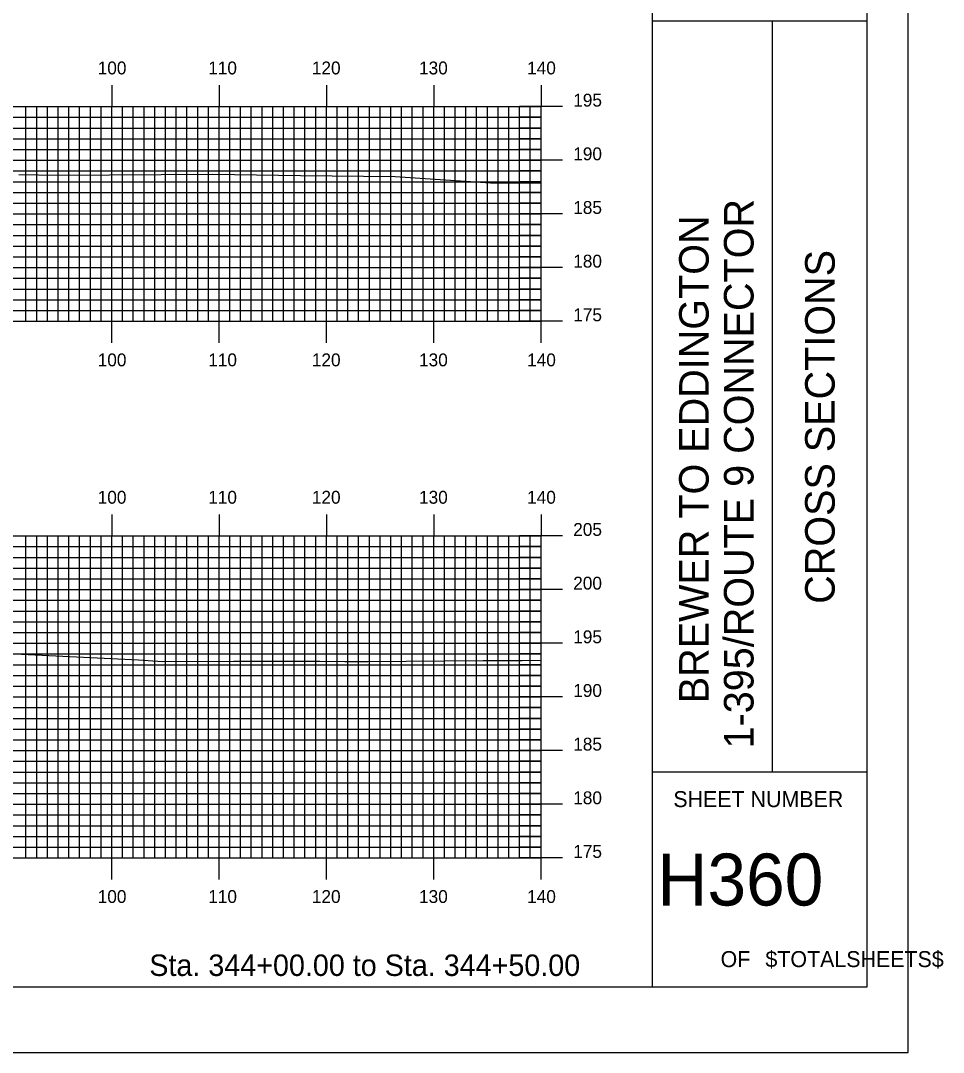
# Model space of a CAD drawing. Extents: x 1825540 to 1825883, y 442591 to 442811.
# Drawn here: x 1825797.4 to 1825883.4, y 442590.5 to 442686.7 of the extents above; entities that cross this region are included whole.
import ezdxf

# ---------------------------------------------------------------- set-up
doc = ezdxf.new("R2010")
doc.units = 0
for name, color, linetype in [('BORDER', 7, 'Continuous'), ('H_V ANNOTATION', 7, 'Continuous'), ('MAJOR', 7, 'Continuous'), ('MINOR', 7, 'Continuous'), ('PLOT BOUNDARY', 7, 'Continuous'), ('S_Roadway_Centerline', 7, 'Continuous')]:
    doc.layers.add(name, color=color, linetype=linetype)

msp = doc.modelspace()

# ---------------------------------------------------------------- linework, layer by layer
at = {"layer": 'BORDER'}
for p, q in [((1825856.274, 442596.665), (1825856.274, 442806.665)), ((1825856.274, 442686.671), (1825876.274, 442686.671)), ((1825867.456, 442616.671), (1825867.456, 442686.671)), ((1825856.274, 442616.671), (1825876.274, 442616.671))]:
    msp.add_line(p, q, dxfattribs=at)
msp.add_lwpolyline([(1825556.274, 442596.665), (1825876.274, 442596.665), (1825876.274, 442806.665), (1825556.274, 442806.665)], close=True, dxfattribs=at)
at = {"layer": 'MAJOR'}
for p, q in [((1825805.874, 442680.669), (1825805.874, 442678.665)), ((1825815.874, 442680.669), (1825815.874, 442678.665)), ((1825825.874, 442680.669), (1825825.874, 442678.665)), ((1825835.874, 442680.669), (1825835.874, 442678.665)), ((1825845.874, 442680.669), (1825845.874, 442678.665)), ((1825565.874, 442678.665), (1825845.874, 442678.665)), ((1825565.874, 442678.665), (1825845.874, 442678.665)), ((1825805.874, 442658.665), (1825805.874, 442678.665)), ((1825815.874, 442658.665), (1825815.874, 442678.665)), ((1825825.874, 442658.665), (1825825.874, 442678.665)), ((1825835.874, 442658.665), (1825835.874, 442678.665)), ((1825847.878, 442678.665), (1825843.87, 442678.665)), ((1825845.874, 442658.665), (1825845.874, 442678.665)), ((1825845.874, 442658.665), (1825845.874, 442678.665)), ((1825565.874, 442673.665), (1825845.874, 442673.665)), ((1825847.878, 442673.665), (1825843.87, 442673.665)), ((1825565.874, 442668.665), (1825845.874, 442668.665)), ((1825847.878, 442668.665), (1825843.87, 442668.665)), ((1825565.874, 442663.665), (1825845.874, 442663.665)), ((1825847.878, 442663.665), (1825843.87, 442663.665)), ((1825565.874, 442658.665), (1825845.874, 442658.665)), ((1825565.874, 442658.665), (1825845.874, 442658.665)), ((1825805.874, 442656.661), (1825805.874, 442658.665)), ((1825815.874, 442656.661), (1825815.874, 442658.665)), ((1825825.874, 442656.661), (1825825.874, 442658.665)), ((1825835.874, 442656.661), (1825835.874, 442658.665)), ((1825847.878, 442658.665), (1825843.87, 442658.665)), ((1825845.874, 442656.661), (1825845.874, 442658.665)), ((1825805.874, 442640.669), (1825805.874, 442638.665)), ((1825815.874, 442640.669), (1825815.874, 442638.665)), ((1825825.874, 442640.669), (1825825.874, 442638.665)), ((1825835.874, 442640.669), (1825835.874, 442638.665)), ((1825845.874, 442640.669), (1825845.874, 442638.665)), ((1825565.874, 442638.665), (1825845.874, 442638.665)), ((1825565.874, 442638.665), (1825845.874, 442638.665)), ((1825805.874, 442608.665), (1825805.874, 442638.665)), ((1825815.874, 442608.665), (1825815.874, 442638.665)), ((1825825.874, 442608.665), (1825825.874, 442638.665)), ((1825835.874, 442608.665), (1825835.874, 442638.665)), ((1825847.878, 442638.665), (1825843.87, 442638.665)), ((1825845.874, 442608.665), (1825845.874, 442638.665)), ((1825845.874, 442608.665), (1825845.874, 442638.665)), ((1825565.874, 442633.665), (1825845.874, 442633.665)), ((1825847.878, 442633.665), (1825843.87, 442633.665)), ((1825565.874, 442628.665), (1825845.874, 442628.665)), ((1825847.878, 442628.665), (1825843.87, 442628.665)), ((1825565.874, 442623.665), (1825845.874, 442623.665)), ((1825847.878, 442623.665), (1825843.87, 442623.665)), ((1825565.874, 442618.665), (1825845.874, 442618.665)), ((1825847.878, 442618.665), (1825843.87, 442618.665)), ((1825565.874, 442613.665), (1825845.874, 442613.665)), ((1825847.878, 442613.665), (1825843.87, 442613.665)), ((1825565.874, 442608.665), (1825845.874, 442608.665)), ((1825565.874, 442608.665), (1825845.874, 442608.665)), ((1825805.874, 442606.661), (1825805.874, 442608.665)), ((1825815.874, 442606.661), (1825815.874, 442608.665)), ((1825825.874, 442606.661), (1825825.874, 442608.665)), ((1825835.874, 442606.661), (1825835.874, 442608.665)), ((1825847.878, 442608.665), (1825843.87, 442608.665)), ((1825845.874, 442606.661), (1825845.874, 442608.665))]:
    msp.add_line(p, q, dxfattribs=at)
at = {"layer": 'MINOR'}
for p, q in [((1825797.874, 442658.665), (1825797.874, 442678.665)), ((1825798.874, 442658.665), (1825798.874, 442678.665)), ((1825799.874, 442658.665), (1825799.874, 442678.665)), ((1825800.874, 442658.665), (1825800.874, 442678.665)), ((1825801.874, 442658.665), (1825801.874, 442678.665)), ((1825802.874, 442658.665), (1825802.874, 442678.665)), ((1825803.874, 442658.665), (1825803.874, 442678.665)), ((1825804.874, 442658.665), (1825804.874, 442678.665)), ((1825806.874, 442658.665), (1825806.874, 442678.665)), ((1825807.874, 442658.665), (1825807.874, 442678.665)), ((1825808.874, 442658.665), (1825808.874, 442678.665)), ((1825809.874, 442658.665), (1825809.874, 442678.665)), ((1825810.874, 442658.665), (1825810.874, 442678.665)), ((1825811.874, 442658.665), (1825811.874, 442678.665)), ((1825812.874, 442658.665), (1825812.874, 442678.665)), ((1825813.874, 442658.665), (1825813.874, 442678.665)), ((1825814.874, 442658.665), (1825814.874, 442678.665)), ((1825816.874, 442658.665), (1825816.874, 442678.665)), ((1825817.874, 442658.665), (1825817.874, 442678.665)), ((1825818.874, 442658.665), (1825818.874, 442678.665)), ((1825819.874, 442658.665), (1825819.874, 442678.665)), ((1825820.874, 442658.665), (1825820.874, 442678.665)), ((1825821.874, 442658.665), (1825821.874, 442678.665)), ((1825822.874, 442658.665), (1825822.874, 442678.665)), ((1825823.874, 442658.665), (1825823.874, 442678.665)), ((1825824.874, 442658.665), (1825824.874, 442678.665)), ((1825826.874, 442658.665), (1825826.874, 442678.665)), ((1825827.874, 442658.665), (1825827.874, 442678.665)), ((1825828.874, 442658.665), (1825828.874, 442678.665)), ((1825829.874, 442658.665), (1825829.874, 442678.665)), ((1825830.874, 442658.665), (1825830.874, 442678.665)), ((1825831.874, 442658.665), (1825831.874, 442678.665)), ((1825832.874, 442658.665), (1825832.874, 442678.665)), ((1825833.874, 442658.665), (1825833.874, 442678.665)), ((1825834.874, 442658.665), (1825834.874, 442678.665)), ((1825836.874, 442658.665), (1825836.874, 442678.665)), ((1825837.874, 442658.665), (1825837.874, 442678.665)), ((1825838.874, 442658.665), (1825838.874, 442678.665)), ((1825839.874, 442658.665), (1825839.874, 442678.665)), ((1825840.874, 442658.665), (1825840.874, 442678.665)), ((1825841.874, 442658.665), (1825841.874, 442678.665)), ((1825842.874, 442658.665), (1825842.874, 442678.665)), ((1825843.874, 442658.665), (1825843.874, 442678.665)), ((1825844.874, 442658.665), (1825844.874, 442678.665)), ((1825565.874, 442677.665), (1825845.874, 442677.665)), ((1825845.874, 442677.665), (1825843.87, 442677.665)), ((1825565.874, 442676.665), (1825845.874, 442676.665)), ((1825845.874, 442676.665), (1825843.87, 442676.665)), ((1825565.874, 442675.665), (1825845.874, 442675.665)), ((1825845.874, 442675.665), (1825843.87, 442675.665)), ((1825565.874, 442674.665), (1825845.874, 442674.665)), ((1825845.874, 442674.665), (1825843.87, 442674.665)), ((1825565.874, 442672.665), (1825845.874, 442672.665)), ((1825845.874, 442672.665), (1825843.87, 442672.665)), ((1825565.874, 442671.665), (1825845.874, 442671.665)), ((1825845.874, 442671.665), (1825843.87, 442671.665)), ((1825565.874, 442670.665), (1825845.874, 442670.665)), ((1825845.874, 442670.665), (1825843.87, 442670.665)), ((1825565.874, 442669.665), (1825845.874, 442669.665)), ((1825845.874, 442669.665), (1825843.87, 442669.665)), ((1825565.874, 442667.665), (1825845.874, 442667.665)), ((1825845.874, 442667.665), (1825843.87, 442667.665)), ((1825565.874, 442666.665), (1825845.874, 442666.665)), ((1825845.874, 442666.665), (1825843.87, 442666.665)), ((1825565.874, 442665.665), (1825845.874, 442665.665)), ((1825845.874, 442665.665), (1825843.87, 442665.665)), ((1825565.874, 442664.665), (1825845.874, 442664.665)), ((1825845.874, 442664.665), (1825843.87, 442664.665)), ((1825565.874, 442662.665), (1825845.874, 442662.665)), ((1825845.874, 442662.665), (1825843.87, 442662.665)), ((1825565.874, 442661.665), (1825845.874, 442661.665)), ((1825845.874, 442661.665), (1825843.87, 442661.665)), ((1825565.874, 442660.665), (1825845.874, 442660.665)), ((1825845.874, 442660.665), (1825843.87, 442660.665)), ((1825565.874, 442659.665), (1825845.874, 442659.665)), ((1825845.874, 442659.665), (1825843.87, 442659.665)), ((1825797.874, 442608.665), (1825797.874, 442638.665)), ((1825798.874, 442608.665), (1825798.874, 442638.665)), ((1825799.874, 442608.665), (1825799.874, 442638.665)), ((1825800.874, 442608.665), (1825800.874, 442638.665)), ((1825801.874, 442608.665), (1825801.874, 442638.665)), ((1825802.874, 442608.665), (1825802.874, 442638.665)), ((1825803.874, 442608.665), (1825803.874, 442638.665)), ((1825804.874, 442608.665), (1825804.874, 442638.665)), ((1825806.874, 442608.665), (1825806.874, 442638.665)), ((1825807.874, 442608.665), (1825807.874, 442638.665)), ((1825808.874, 442608.665), (1825808.874, 442638.665)), ((1825809.874, 442608.665), (1825809.874, 442638.665)), ((1825810.874, 442608.665), (1825810.874, 442638.665)), ((1825811.874, 442608.665), (1825811.874, 442638.665)), ((1825812.874, 442608.665), (1825812.874, 442638.665)), ((1825813.874, 442608.665), (1825813.874, 442638.665)), ((1825814.874, 442608.665), (1825814.874, 442638.665)), ((1825816.874, 442608.665), (1825816.874, 442638.665)), ((1825817.874, 442608.665), (1825817.874, 442638.665)), ((1825818.874, 442608.665), (1825818.874, 442638.665)), ((1825819.874, 442608.665), (1825819.874, 442638.665)), ((1825820.874, 442608.665), (1825820.874, 442638.665)), ((1825821.874, 442608.665), (1825821.874, 442638.665)), ((1825822.874, 442608.665), (1825822.874, 442638.665)), ((1825823.874, 442608.665), (1825823.874, 442638.665)), ((1825824.874, 442608.665), (1825824.874, 442638.665)), ((1825826.874, 442608.665), (1825826.874, 442638.665)), ((1825827.874, 442608.665), (1825827.874, 442638.665)), ((1825828.874, 442608.665), (1825828.874, 442638.665)), ((1825829.874, 442608.665), (1825829.874, 442638.665)), ((1825830.874, 442608.665), (1825830.874, 442638.665)), ((1825831.874, 442608.665), (1825831.874, 442638.665)), ((1825832.874, 442608.665), (1825832.874, 442638.665)), ((1825833.874, 442608.665), (1825833.874, 442638.665)), ((1825834.874, 442608.665), (1825834.874, 442638.665)), ((1825836.874, 442608.665), (1825836.874, 442638.665)), ((1825837.874, 442608.665), (1825837.874, 442638.665)), ((1825838.874, 442608.665), (1825838.874, 442638.665)), ((1825839.874, 442608.665), (1825839.874, 442638.665)), ((1825840.874, 442608.665), (1825840.874, 442638.665)), ((1825841.874, 442608.665), (1825841.874, 442638.665)), ((1825842.874, 442608.665), (1825842.874, 442638.665)), ((1825843.874, 442608.665), (1825843.874, 442638.665)), ((1825844.874, 442608.665), (1825844.874, 442638.665)), ((1825565.874, 442637.665), (1825845.874, 442637.665)), ((1825845.874, 442637.665), (1825843.87, 442637.665)), ((1825565.874, 442636.665), (1825845.874, 442636.665)), ((1825845.874, 442636.665), (1825843.87, 442636.665)), ((1825565.874, 442635.665), (1825845.874, 442635.665)), ((1825845.874, 442635.665), (1825843.87, 442635.665)), ((1825565.874, 442634.665), (1825845.874, 442634.665)), ((1825845.874, 442634.665), (1825843.87, 442634.665)), ((1825565.874, 442632.665), (1825845.874, 442632.665)), ((1825845.874, 442632.665), (1825843.87, 442632.665)), ((1825565.874, 442631.665), (1825845.874, 442631.665)), ((1825845.874, 442631.665), (1825843.87, 442631.665)), ((1825565.874, 442630.665), (1825845.874, 442630.665)), ((1825845.874, 442630.665), (1825843.87, 442630.665)), ((1825565.874, 442629.665), (1825845.874, 442629.665)), ((1825845.874, 442629.665), (1825843.87, 442629.665)), ((1825565.874, 442627.665), (1825845.874, 442627.665)), ((1825845.874, 442627.665), (1825843.87, 442627.665)), ((1825565.874, 442626.665), (1825845.874, 442626.665)), ((1825845.874, 442626.665), (1825843.87, 442626.665)), ((1825565.874, 442625.665), (1825845.874, 442625.665)), ((1825845.874, 442625.665), (1825843.87, 442625.665)), ((1825565.874, 442624.665), (1825845.874, 442624.665)), ((1825845.874, 442624.665), (1825843.87, 442624.665)), ((1825565.874, 442622.665), (1825845.874, 442622.665)), ((1825845.874, 442622.665), (1825843.87, 442622.665)), ((1825565.874, 442621.665), (1825845.874, 442621.665)), ((1825845.874, 442621.665), (1825843.87, 442621.665)), ((1825565.874, 442620.665), (1825845.874, 442620.665)), ((1825845.874, 442620.665), (1825843.87, 442620.665)), ((1825565.874, 442619.665), (1825845.874, 442619.665)), ((1825845.874, 442619.665), (1825843.87, 442619.665)), ((1825565.874, 442617.665), (1825845.874, 442617.665)), ((1825845.874, 442617.665), (1825843.87, 442617.665)), ((1825565.874, 442616.665), (1825845.874, 442616.665)), ((1825845.874, 442616.665), (1825843.87, 442616.665)), ((1825565.874, 442615.665), (1825845.874, 442615.665)), ((1825845.874, 442615.665), (1825843.87, 442615.665)), ((1825565.874, 442614.665), (1825845.874, 442614.665)), ((1825845.874, 442614.665), (1825843.87, 442614.665)), ((1825565.874, 442612.665), (1825845.874, 442612.665)), ((1825845.874, 442612.665), (1825843.87, 442612.665)), ((1825565.874, 442611.665), (1825845.874, 442611.665)), ((1825845.874, 442611.665), (1825843.87, 442611.665)), ((1825565.874, 442610.665), (1825845.874, 442610.665)), ((1825845.874, 442610.665), (1825843.87, 442610.665)), ((1825565.874, 442609.665), (1825845.874, 442609.665)), ((1825845.874, 442609.665), (1825843.87, 442609.665))]:
    msp.add_line(p, q, dxfattribs=at)
at = {"layer": 'PLOT BOUNDARY'}
msp.add_lwpolyline([(1825540.087, 442590.547), (1825880.087, 442590.547), (1825880.087, 442810.547), (1825540.087, 442810.547)], close=True, dxfattribs=at)
msp.add_lwpolyline([(1825540.087, 442590.547), (1825880.087, 442590.547), (1825880.087, 442810.547), (1825540.087, 442810.547)], close=True, dxfattribs=at)
at = {"layer": 'S_Roadway_Centerline'}
for points in [[(1825797.221, 442672.353), (1825800.871, 442672.29), (1825815.248, 442672.374), (1825823.447, 442672.251), (1825832.287, 442672.15), (1825841.17, 442671.575), (1825845.874, 442671.516)], [(1825794.838, 442627.759), (1825808.349, 442627.133), (1825810.594, 442626.959), (1825817.233, 442626.987), (1825825.261, 442626.99), (1825827.603, 442626.963), (1825829.745, 442626.972), (1825840.469, 442627.06), (1825844.131, 442627.064), (1825845.874, 442627.082)]]:
    msp.add_lwpolyline(points, dxfattribs=at)

# ---------------------------------------------------------------- texts
at = {"layer": 'BORDER'}
for s, p in [('1-395/ROUTE 9 CONNECTOR', (1825865.678, 442618.865)), ('BREWER TO EDDINGTON', (1825861.498, 442623.074)), ('CROSS SECTIONS', (1825873.243, 442632.339))]:
    msp.add_text(s, height=2.75575, rotation=90, dxfattribs=at).set_placement(p)
for s, height, p in [('SHEET NUMBER', 1.49054, (1825858.205, 442613.398)), ('H360', 4.8388, (1825856.713, 442604.23)), ('OF', 1.4905, (1825862.608, 442598.491)), ('$TOTALSHEETS$', 1.49054, (1825866.787, 442598.491))]:
    msp.add_text(s, height=height, dxfattribs=at).set_placement(p)
at = {"layer": 'H_V ANNOTATION'}
for s, height, p in [('100', 1.2, (1825804.557, 442681.665)), ('110', 1.2, (1825814.857, 442681.665)), ('120', 1.2, (1825824.515, 442681.665)), ('130', 1.2, (1825834.504, 442681.665)), ('140', 1.2, (1825844.579, 442681.665)), ('195', 1.2, (1825848.874, 442678.665)), ('190', 1.2, (1825848.874, 442673.665)), ('185', 1.2, (1825848.874, 442668.665)), ('180', 1.2, (1825848.874, 442663.665)), ('175', 1.2, (1825848.874, 442658.665)), ('100', 1.2, (1825804.557, 442654.465)), ('110', 1.2, (1825814.857, 442654.465)), ('120', 1.2, (1825824.515, 442654.465)), ('130', 1.2, (1825834.504, 442654.465)), ('140', 1.2, (1825844.579, 442654.465)), ('100', 1.2, (1825804.557, 442641.665)), ('110', 1.2, (1825814.857, 442641.665)), ('120', 1.2, (1825824.515, 442641.665)), ('130', 1.2, (1825834.504, 442641.665)), ('140', 1.2, (1825844.579, 442641.665)), ('205', 1.2, (1825848.874, 442638.665)), ('200', 1.2, (1825848.874, 442633.665)), ('195', 1.2, (1825848.874, 442628.665)), ('190', 1.2, (1825848.874, 442623.665)), ('185', 1.2, (1825848.874, 442618.665)), ('180', 1.2, (1825848.874, 442613.665)), ('175', 1.2, (1825848.874, 442608.665)), ('100', 1.2, (1825804.557, 442604.465)), ('110', 1.2, (1825814.857, 442604.465)), ('120', 1.2, (1825824.515, 442604.465)), ('130', 1.2, (1825834.504, 442604.465)), ('140', 1.2, (1825844.579, 442604.465)), ('Sta. 344+00.00 to Sta. 344+50.00', 2.0004, (1825809.366, 442597.665))]:
    msp.add_text(s, height=height, dxfattribs=at).set_placement(p)

doc.saveas('drawing.dxf')
